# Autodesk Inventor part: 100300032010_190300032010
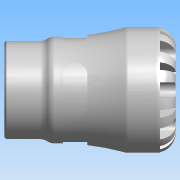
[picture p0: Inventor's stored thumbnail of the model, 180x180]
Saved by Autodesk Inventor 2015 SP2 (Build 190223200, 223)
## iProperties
Created: 2016-12
Part Number: 100300032010_190300032010
Material: PVC-Piping
Description: PLASSON FEMALE ADAPTOR 32X1" SERIES 1
Document SubType Name: Modeling
Designer: KIM
Mass: 664.223 g
Surface Area: 733.008 cm^2
Volume: 474.445 cm^3
Density: 1.4 g/cm^3
Appearance: Smooth - White
Author: KIM
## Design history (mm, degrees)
derived "1003.ipt"
feature "Solid1::1003.ipt"
tag "TaggingFeature1"
body "Solid1"
other parameters: "d0" = 79, "d1" = 22.68, "d2" = 32, "d4" = 58, "d6" = 54, "d8" = 49.3, "d13" = 7.2, "d14" = 7.2, "d15" = 0, "d17" = 360 deg, "d19" = 8 deg, "d20" = 0.64, "d21" = 0.64, "d22" = 8 deg, "d24" = 0, "d26" = 360 deg, "d32" = 5.8, "d33" = 5.8, "d39" = 0.90873, "d42" = 30.291, "d43" = 45.24, "d46" = 2.66667, "d47" = 21, "d48" = 28.77645, "d50" = 1.32, "d51" = 0.58, "d54" = 11.2, "d55" = 7.04, "d57" = 14.112, "d58" = 0, "d68" = 360 deg, "d72" = 0.64, "d74" = 0, "d76" = 9.52, "d_" = 32, "E_" = 58, "H_" = 79, "l_" = 54, "Rp" = 30.291, "l_2" = 21, "d9" = 9, "d11" = 58, "d49" = 4
